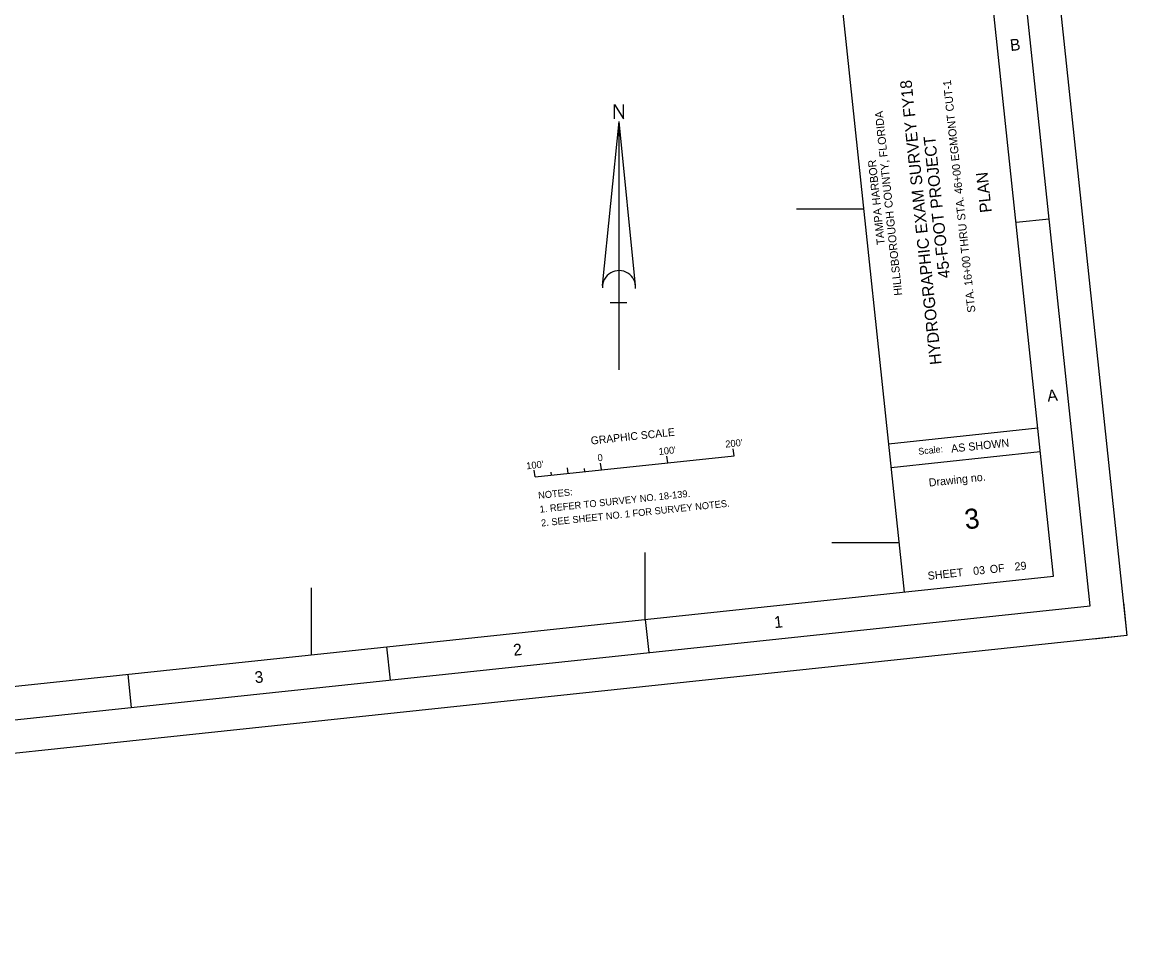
# Model space of a CAD drawing. Extents: x 338488 to 343222, y 1183896 to 1187741.
# Drawn here: x 341566 to 343222, y 1183896 to 1185280 of the extents above; entities that cross this region are included whole.
import ezdxf

# ---------------------------------------------------------------- set-up
doc = ezdxf.new("R2010")
doc.units = 0
for name, color, linetype in [('G-ANNO-NPLT', 7, 'Continuous'), ('G-ANNO-TEXT-DRWG', 7, 'Continuous'), ('G-ANNO-TEXT-PROJ', 7, 'Continuous'), ('G-ANNO-TEXT-TTLB', 7, 'Continuous'), ('G-ANNO-TTLB', 7, 'Continuous'), ('V-ANNO-NOTE', 7, 'Continuous'), ('V-ANNO-SYMB', 7, 'Continuous'), ('V-TOPO-COOR-STAT', 7, 'Continuous')]:
    doc.layers.add(name, color=color, linetype=linetype)

msp = doc.modelspace()

# ---------------------------------------------------------------- linework, layer by layer
at = {"layer": 'G-ANNO-NPLT'}
msp.add_lwpolyline([(338488.3, 1187277.4), (342863.7, 1187741.2), (343222.1, 1184360.2), (338846.6, 1183896.4)], close=True, dxfattribs=at)
msp.add_lwpolyline([(343216.8, 1184409.9), (343222.1, 1184360.2), (343172.4, 1184354.9)], dxfattribs=at)
at = {"layer": 'G-ANNO-TTLB'}
for p, q in [((342551, 1187607.5), (342888.4, 1184425.4)), ((343105.6, 1184984.7), (343055.9, 1184979.4)), ((342864.8, 1184647.9), (343088.5, 1184671.6)), ((342868.5, 1184612.4), (343092.3, 1184636.1)), ((342505.8, 1184334.6), (342500.6, 1184384.3)), ((342118, 1184293.4), (342112.7, 1184343.2)), ((341730.2, 1184252.3), (341724.9, 1184302.1))]:
    msp.add_line(p, q, dxfattribs=at)
for points in [[(338891.1, 1183951.4), (343167.1, 1184404.6), (342819.3, 1187686.2), (338543.3, 1187233)], [(342774.8, 1187631.3), (338672.8, 1187196.4), (339010.1, 1184014.3), (343112.1, 1184449.1)]]:
    msp.add_lwpolyline(points, close=True, dxfattribs=at)
at = {"layer": 'V-ANNO-NOTE'}
for p, q in [((342633.2, 1184629.6), (342632.1, 1184640)), ((342334.9, 1184598), (342633.2, 1184629.6)), ((342434.3, 1184608.5), (342433.2, 1184618.9)), ((342434.3, 1184608.5), (342433.2, 1184618.9)), ((342434.3, 1184608.5), (342433.8, 1184613.5)), ((342533.8, 1184619), (342532.7, 1184629.4)), ((342334.9, 1184598), (342333.8, 1184608.3)), ((342359.7, 1184600.6), (342359.2, 1184605.4)), ((342384.6, 1184603.2), (342383.7, 1184611.7)), ((342409.5, 1184605.9), (342408.9, 1184610.6))]:
    msp.add_line(p, q, dxfattribs=at)
at = {"layer": 'V-ANNO-SYMB'}
for p, q in [((342436.1, 1184885.1), (342460.8, 1185130.9)), ((342460.8, 1184758.6), (342460.8, 1185130.9)), ((342485.5, 1184885.1), (342460.8, 1185130.9)), ((342472.5, 1184859.1), (342447.7, 1184859.1))]:
    msp.add_line(p, q, dxfattribs=at)
msp.add_lwpolyline([(342453.9, 1185134.9), (342453.9, 1185156.6), (342467.4, 1185134.9), (342467.4, 1185156.6)], dxfattribs=at)
msp.add_arc((342460.8, 1184882.7), 24.8, 355.2984, 182.0673, dxfattribs=at)
at = {"layer": 'V-TOPO-COOR-STAT'}
for p, q in [((342726.9, 1185000), (342827.4, 1185000)), ((342779.9, 1184500), (342880.4, 1184500)), ((342500, 1184384.2), (342500, 1184484.8)), ((342000, 1184331.2), (342000, 1184431.8))]:
    msp.add_line(p, q, dxfattribs=at)

# ---------------------------------------------------------------- texts
at = {"layer": 'G-ANNO-TEXT-DRWG'}
for s, height, rotation, p in [('STA. 16+00 THRU STA. 46+00 EGMONT CUT-1', 12, 96.0506, (342995.1, 1184845.2)), ('PLAN', 17.5, 96.0506, (343019.6, 1184995.2)), ('3', 30, 6.0506, (342980.3, 1184519.4)), (' 03          29', 12, 6.0506, (342987.8, 1184450.5))]:
    msp.add_text(s, height=height, rotation=rotation, dxfattribs=at).set_placement(p)
at = {"layer": 'G-ANNO-TEXT-PROJ'}
for s, height, p in [('HYDROGRAPHIC EXAM SURVEY FY18', 17.5, (342944.4, 1184767.2)), ('HILLSBOROUGH COUNTY, FLORIDA', 12, (342885.4, 1184870.6)), ('45-FOOT PROJECT', 17.5, (342957.1, 1184896.8)), ('TAMPA HARBOR', 12, (342859.3, 1184946.6))]:
    msp.add_text(s, height=height, rotation=96.0506, dxfattribs=at).set_placement(p)
at = {"layer": 'G-ANNO-TEXT-TTLB'}
for s, height, p in [('AS SHOWN', 12, (342959.2, 1184634.5)), ('Scale:', 10, (342909.9, 1184631.2)), ('Drawing no.', 12, (342925.7, 1184583.6)), ('SHEET         OF', 12, (342924.1, 1184443.7))]:
    msp.add_text(s, height=height, rotation=6.0506, dxfattribs=at).set_placement(p)
at = {"layer": 'G-ANNO-TTLB'}
for s, p in [('B', (343047.8, 1185236.6)), ('A', (343103.5, 1184710.8)), ('1', (342694.1, 1184371.3)), ('2', (342303.1, 1184329.8)), ('3', (341915.5, 1184288.7))]:
    msp.add_text(s, height=17.5, rotation=6.0506, dxfattribs=at).set_placement(p)
at = {"layer": 'V-ANNO-NOTE'}
for s, height, p in [('GRAPHIC SCALE', 11.666, (342419, 1184646.6)), ("200'", 10.42, (342620.7, 1184642)), ('0', 10.4, (342429.2, 1184621.4)), ("100'", 10.42, (342520.8, 1184630.9)), ("100'", 10.42, (342322.3, 1184609.4)), ('NOTES:', 10.42, (342340.1, 1184565.1)), ('1. REFER TO SURVEY NO. 18-139.', 10.416, (342342.3, 1184544.4)), ('2. SEE SHEET NO. 1 FOR SURVEY NOTES.', 10.416, (342344.5, 1184523.7))]:
    msp.add_text(s, height=height, rotation=6.0506, dxfattribs=at).set_placement(p)

doc.saveas('drawing.dxf')
